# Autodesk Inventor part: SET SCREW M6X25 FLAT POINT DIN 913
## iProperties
IsCustomPart: 1
Created: 2006-02
Part Number: SET SCREW M6X25 FLAT POINT DIN 913
Material: Steel, Mild
Description: Hexagon Socket Set Screw
Document SubType Name: Modeling
Standard: DIN 913
Designer: Andy Moles
Standards Organization: DIN
Language: en-US
Size Designation: M6 x 25
Categories: <MemberInstance><Categories><Category DisplayName="Fasteners" InternalName="e4da775c-781d-43d5-af7c-5136215cf5a6" Mnemonic="FSTN"><Category DisplayName="Bolts"
Density: 1 g/cm^3
Author: Andy Moles
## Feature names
1. Body [Revolution]
2. Slot [Extrusion]
3. Chamfer1
4. Chamfer2
